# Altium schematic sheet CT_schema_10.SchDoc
size 274 x 160 mm
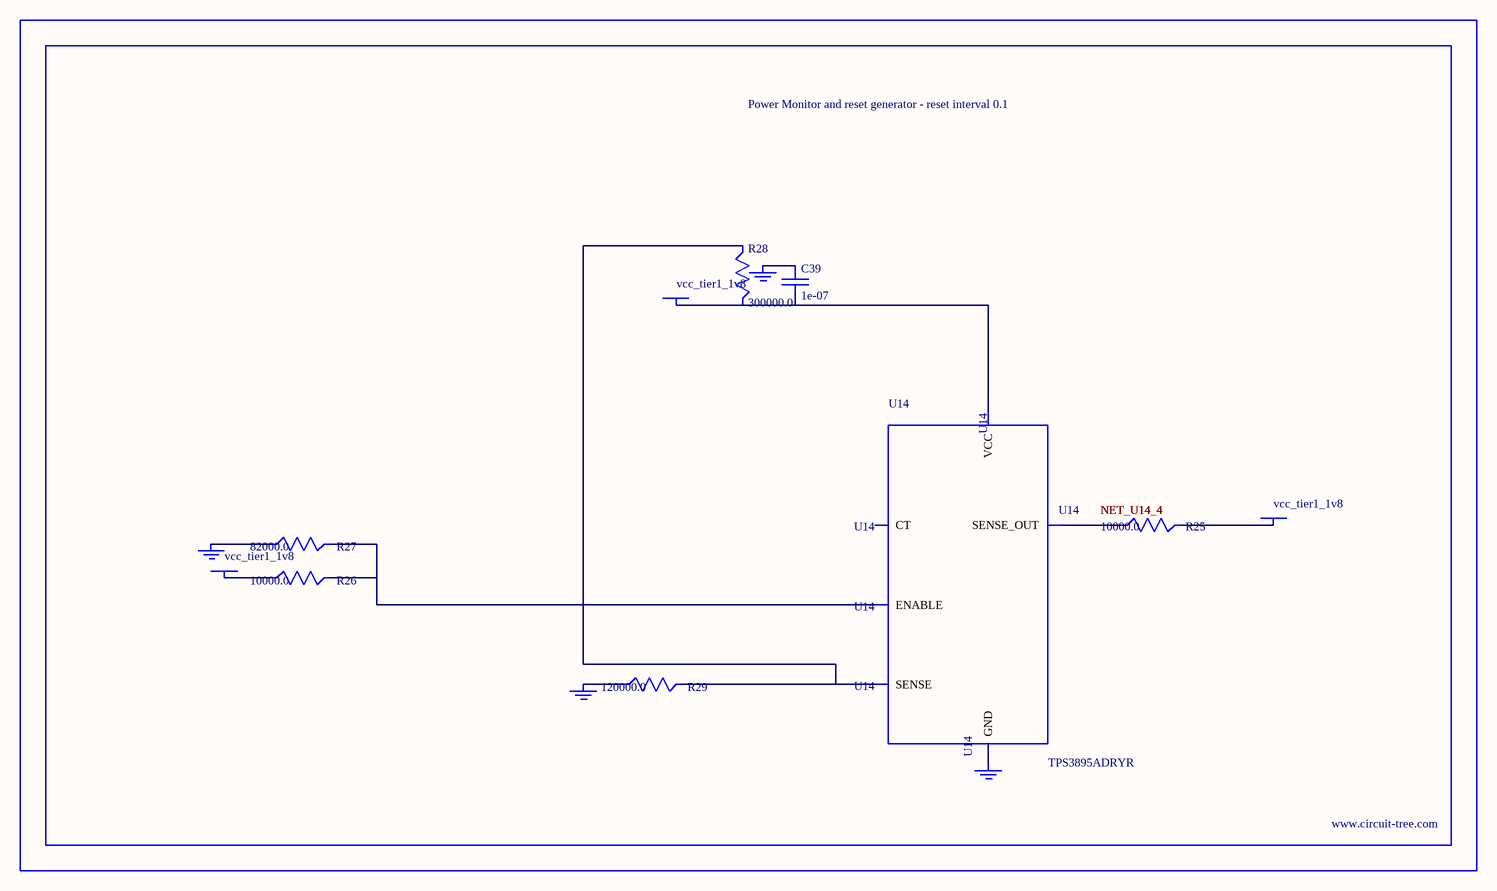
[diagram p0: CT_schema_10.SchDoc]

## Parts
BORDER9  (no value)
C39  1e-07  [C0402]
GND_INSTANCE_9_0  (no value)
GND_INSTANCE_9_1  (no value)
GND_INSTANCE_9_2  (no value)
GND_INSTANCE_9_3  (no value)
POWER_INSTANCE_9_0  vcc_tier1_1v8
POWER_INSTANCE_9_1  vcc_tier1_1v8
POWER_INSTANCE_9_2  vcc_tier1_1v8
R25  10000.0  [R0603]
R26  10000.0  [R0603]
R27  82000.0  [R0603]
R28  300000.0  [R0603]
R29  120000.0  [R0603]
U14  TPS3895ADRYR  [SON-6]

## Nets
NetC39_1: C39.1 GND_INSTANCE_9_2.0(GND)
NetC39_2: C39.2 POWER_INSTANCE_9_2.0(PWR) R28.2 U14.6(VCC)
NetGND_INSTANCE_9_0_0: GND_INSTANCE_9_0.0(GND) R27.1
NetGND_INSTANCE_9_1_0: GND_INSTANCE_9_1.0(GND) R29.1
NetGND_INSTANCE_9_3_0: GND_INSTANCE_9_3.0(GND) U14.2(GND)
NetPOWER_INSTANCE_9_0_0: POWER_INSTANCE_9_0.0(PWR) R26.1
NetPOWER_INSTANCE_9_1_0: POWER_INSTANCE_9_1.0(PWR) R25.2
NetR25_1: R25.1 U14.4(SENSE_OUT)
NetR26_2: R26.2 R27.2 U14.1(ENABLE)
NetR28_1: R28.1 R29.2 U14.3(SENSE)

Not connected (* = marked no-connect by the designer): U14 5(CT)

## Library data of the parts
BORDER9 = BORDER_PAGE9
C39 = C0402C104K3RACTU
GND_INSTANCE_9_0-GND_INSTANCE_9_3 = GND
POWER_INSTANCE_9_0-POWER_INSTANCE_9_2 = PWR
R25 R26 = RC0603JR-0710KL
R27 = RC0603JR-0782KL
R28 = RC0603JR-07300KL
R29 = RC0603JR-07120KL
